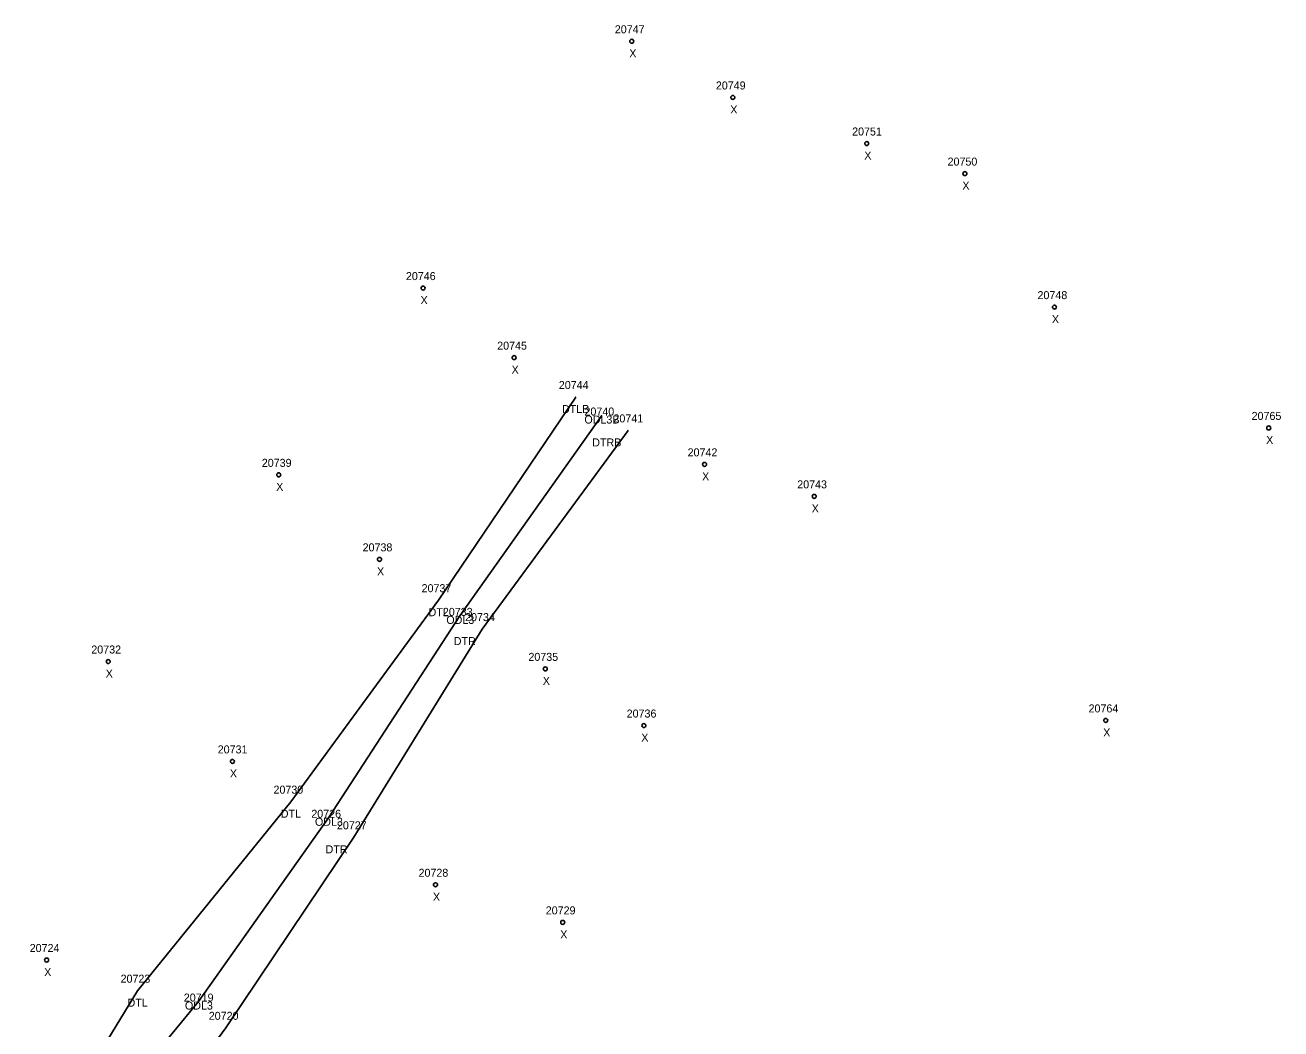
# Model space of a CAD drawing. Extents: x 1966740 to 1969291, y 1117378 to 1118461.
# Drawn here: x 1968871.7 to 1969028.7, y 1117943.2 to 1118068.6 of the extents above; entities that cross this region are included whole.
import ezdxf

# ---------------------------------------------------------------- set-up
doc = ezdxf.new("R2010")
doc.units = 0
for name, color, linetype in [('RD_EX_H2O', 7, 'Continuous'), ('RD_EX_H2O_txCode', 7, 'Continuous'), ('RD_SMD_Locator', 7, 'Continuous'), ('RD_SMD_Misc', 7, 'Continuous')]:
    doc.layers.add(name, color=color, linetype=linetype)

msp = doc.modelspace()

# ---------------------------------------------------------------- linework, layer by layer
at = {"layer": 'RD_EX_H2O'}
for points in [[(1968872.44, 1117926.13), (1968885.78, 1117948), (1968904.93, 1117971.61), (1968923.41, 1117996.78), (1968940.56, 1118022.16)], [(1968871.74, 1117920.38), (1968873.64, 1117922.68), (1968893.41, 1117946.64), (1968909.65, 1117969.6), (1968926.07, 1117994.82), (1968943.8, 1118019.85)], [(1968882.13, 1117923.29), (1968896.84, 1117943.36), (1968912.83, 1117967.16), (1968928.85, 1117993.17), (1968947.1, 1118017.99)]]:
    msp.add_lwpolyline(points, dxfattribs=at)
at = {"layer": 'RD_SMD_Locator'}
for centre, radius in [((1968947.56, 1118066.6), 0.25), ((1968960.19, 1118059.58), 0.25), ((1968976.93, 1118053.83), 0.25), ((1968989.19, 1118050.07), 0.25), ((1968921.48, 1118035.77), 0.25), ((1969000.39, 1118033.39), 0.25), ((1968932.86, 1118027.08), 0.25), ((1968940.56, 1118022.16), 0.001), ((1968943.8, 1118019.85), 0.001), ((1969027.17, 1118018.3), 0.25), ((1968947.1, 1118017.99), 0.001), ((1968956.66, 1118013.75), 0.25), ((1968903.44, 1118012.44), 0.25), ((1968970.36, 1118009.75), 0.25), ((1968916.03, 1118001.88), 0.25), ((1968923.41, 1117996.78), 0.001), ((1968926.07, 1117994.82), 0.001), ((1968928.85, 1117993.17), 0.001), ((1968882.12, 1117989.12), 0.25), ((1968936.75, 1117988.2), 0.25), ((1969006.8, 1117981.76), 0.25), ((1968949.07, 1117981.12), 0.25), ((1968897.65, 1117976.64), 0.25), ((1968904.93, 1117971.61), 0.001), ((1968909.65, 1117969.6), 0.001), ((1968912.83, 1117967.16), 0.001), ((1968923.03, 1117961.23), 0.25), ((1968938.93, 1117956.53), 0.25), ((1968874.43, 1117951.83), 0.25), ((1968885.78, 1117948), 0.001), ((1968893.41, 1117946.64), 0.001), ((1968896.84, 1117943.36), 0.001)]:
    msp.add_circle(centre, radius, dxfattribs=at)

# ---------------------------------------------------------------- texts
at = {"layer": 'RD_EX_H2O_txCode'}
for s, p in [('20744', (1968938.44, 1118023.16)), ('DTLB', (1968938.84, 1118020.16)), ('ODL3B', (1968941.64, 1118018.85)), ('20740', (1968941.65, 1118019.85)), ('20741', (1968945.27, 1118018.99)), ('DTRB', (1968942.62, 1118015.99)), ('20737', (1968921.29, 1117997.78)), ('DTL', (1968922.16, 1117994.78)), ('20733', (1968923.95, 1117994.82)), ('ODL3', (1968924.38, 1117993.82)), ('20734', (1968926.73, 1117994.17)), ('DTR', (1968925.31, 1117991.17)), ('20730', (1968902.78, 1117972.61)), ('DTL', (1968903.69, 1117969.61)), ('20726', (1968907.51, 1117969.6)), ('ODL3', (1968907.96, 1117968.6)), ('20727', (1968910.71, 1117968.16)), ('DTR', (1968909.29, 1117965.16)), ('20723', (1968883.67, 1117949)), ('20719', (1968891.57, 1117946.64)), ('DTL', (1968884.54, 1117946)), ('ODL3', (1968891.71, 1117945.64)), ('20720', (1968894.69, 1117944.36))]:
    msp.add_text(s, height=1, dxfattribs=at).set_placement(p)
at = {"layer": 'RD_SMD_Misc'}
for s, p in [('20747', (1968945.44, 1118067.6)), ('X', (1968947.25, 1118064.6)), ('20749', (1968958.07, 1118060.58)), ('X', (1968959.87, 1118057.58)), ('20751', (1968975.1, 1118054.83)), ('X', (1968976.62, 1118051.83)), ('20750', (1968987.03, 1118051.07)), ('X', (1968988.88, 1118048.07)), ('20746', (1968919.33, 1118036.77)), ('20748', (1968998.27, 1118034.39)), ('X', (1968921.16, 1118033.77)), ('X', (1969000.07, 1118031.39)), ('20745', (1968930.74, 1118028.08)), ('X', (1968932.54, 1118025.08)), ('20765', (1969025.03, 1118019.3)), ('X', (1969026.85, 1118016.3)), ('20742', (1968954.54, 1118014.75)), ('20739', (1968901.32, 1118013.44)), ('X', (1968956.35, 1118011.75)), ('20743', (1968968.24, 1118010.75)), ('X', (1968903.12, 1118010.44)), ('X', (1968970.05, 1118007.75)), ('20738', (1968913.92, 1118002.88)), ('X', (1968915.72, 1117999.88)), ('20732', (1968880.01, 1117990.12)), ('20735', (1968934.64, 1117989.2)), ('X', (1968881.81, 1117987.12)), ('X', (1968936.44, 1117986.2)), ('20764', (1969004.65, 1117982.76)), ('20736', (1968946.92, 1117982.12)), ('X', (1969006.48, 1117979.76)), ('X', (1968948.75, 1117979.12)), ('20731', (1968895.81, 1117977.64)), ('X', (1968897.33, 1117974.64)), ('20728', (1968920.91, 1117962.23)), ('X', (1968922.71, 1117959.23)), ('20729', (1968936.81, 1117957.53)), ('X', (1968938.62, 1117954.53)), ('20724', (1968872.31, 1117952.83)), ('X', (1968874.12, 1117949.83))]:
    msp.add_text(s, height=1, dxfattribs=at).set_placement(p)

doc.saveas('drawing.dxf')
